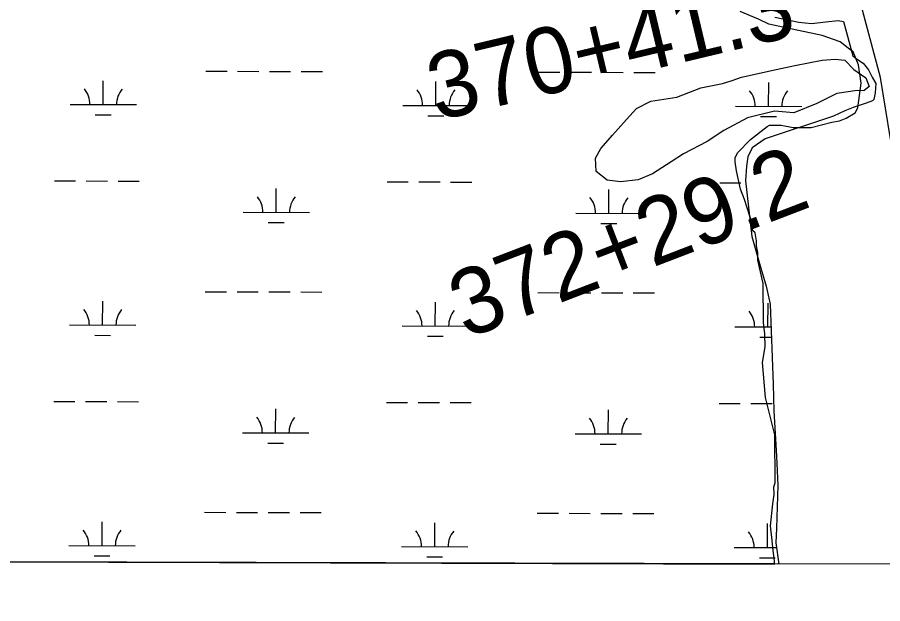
# Model space of a CAD drawing. Extents: x 3161665 to 3199565, y 885729 to 911164.
# Drawn here: x 3174412 to 3175718, y 891109 to 891993 of the extents above; entities that cross this region are included whole.
import ezdxf

# ---------------------------------------------------------------- set-up
doc = ezdxf.new("R2010")
doc.units = 0
for name, color, linetype in [('V-GRID-FRAM', 7, 'Continuous'), ('V-SITE-VEGE', 7, 'Continuous'), ('V-SURV-IDEN', 7, 'Continuous'), ('V-TOPO-SHOR', 7, 'Continuous'), ('V-WETL-SWMP', 7, 'Continuous')]:
    doc.layers.add(name, color=color, linetype=linetype)

msp = doc.modelspace()

# ---------------------------------------------------------------- linework, layer by layer
at = {"layer": 'V-GRID-FRAM'}
msp.add_lwpolyline([(3165935.6, 909383.8), (3197271.3, 909297.2), (3197229, 891108.8), (3165877.4, 891195.5), (3165935.6, 909383.8)], dxfattribs=at)
at = {"layer": 'V-SITE-VEGE'}
for p, q in [((3175530.5, 891990.7), (3175503, 892002.2)), ((3175546.2, 891983), (3175530.5, 891990.7)), ((3175581.4, 891975.5), (3175546.2, 891983)), ((3175626.5, 891966), (3175581.4, 891975.5)), ((3175653.9, 891956.5), (3175626.5, 891966)), ((3175665.7, 891946.8), (3175653.9, 891956.5)), ((3175673.6, 891941), (3175665.7, 891946.8)), ((3175681.6, 891921.5), (3175673.6, 891941)), ((3175685.7, 891894.2), (3175681.6, 891921.5)), ((3175680.2, 891857), (3175685.7, 891894.2)), ((3175662.7, 891841.2), (3175676.3, 891849.2)), ((3175676.3, 891849.2), (3175680.2, 891857)), ((3175610, 891827.1), (3175641.2, 891835.2)), ((3175641.2, 891835.2), (3175653, 891837.2)), ((3175653, 891837.2), (3175662.7, 891841.2)), ((3175518.3, 891808.8), (3175543.5, 891828.5)), ((3175543.5, 891828.5), (3175547.4, 891830.5)), ((3175547.4, 891830.5), (3175565, 891830.6)), ((3175565, 891830.6), (3175582.7, 891826.9)), ((3175582.7, 891826.9), (3175610, 891827.1)), ((3175498.9, 891789), (3175518.3, 891808.8)), ((3175495.1, 891781.2), (3175498.9, 891789)), ((3175495.1, 891775.3), (3175495.1, 891781.2)), ((3175497.2, 891761.7), (3175495.1, 891775.3)), ((3175503.3, 891734.3), (3175497.2, 891761.7)), ((3175509.3, 891718.7), (3175503.3, 891734.3)), ((3175517.3, 891693.4), (3175509.3, 891718.7)), ((3175521.3, 891681.7), (3175517.3, 891693.4)), ((3175521.4, 891671.9), (3175521.3, 891681.7)), ((3175525.3, 891668), (3175521.4, 891671.9)), ((3175527.4, 891656.3), (3175525.3, 891668)), ((3175527.4, 891648.5), (3175527.4, 891656.3)), ((3175529.5, 891638.8), (3175527.4, 891648.5)), ((3175529.6, 891627), (3175529.5, 891638.8)), ((3175537.7, 891591.9), (3175529.6, 891627)), ((3175538.2, 891533.2), (3175537.7, 891591.9)), ((3175540.3, 891515.7), (3175538.2, 891533.2)), ((3175540.4, 891496.1), (3175540.3, 891515.7)), ((3175536.7, 891472.6), (3175540.4, 891496.1)), ((3175541, 891419.9), (3175536.7, 891472.6)), ((3175555.2, 891363.3), (3175541, 891419.9)), ((3175555.8, 891291), (3175555.2, 891363.3)), ((3175553.9, 891285.1), (3175555.8, 891291)), ((3175552.1, 891259.7), (3175554, 891273.4)), ((3175554, 891273.4), (3175553.9, 891285.1)), ((3175548.5, 891226.4), (3175552.1, 891259.7)), ((3175550.6, 891208.8), (3175548.5, 891226.4)), ((3175552.7, 891189.3), (3175550.6, 891208.8)), ((3175554.8, 891173.7), (3175552.7, 891189.3)), ((3173270.6, 891175), (3175554.8, 891168.7)), ((3175554.8, 891168.7), (3175554.8, 891173.7))]:
    msp.add_line(p, q, dxfattribs=at)
at = {"layer": 'V-TOPO-SHOR'}
for points in [[(3175838, 891169.7), (3175813.2, 891379.1), (3175771.5, 891612.2), (3175729.7, 891809.8), (3175714.7, 891902.7), (3175685.4, 892011.6), (3175682.1, 892023.4)], [(3175307.5, 891811.8), (3175310.3, 891815.4), (3175331.6, 891839.3), (3175346.6, 891855.9), (3175368, 891866.9), (3175407.5, 891873), (3175443.3, 891886.9), (3175476.3, 891893.6), (3175490.6, 891898.1), (3175504.9, 891903.2), (3175557.3, 891914.4), (3175585.2, 891920.4), (3175626.8, 891928.6), (3175646.2, 891930.2), (3175660.6, 891928.9), (3175674.4, 891914.7), (3175692.4, 891901.9), (3175697.6, 891889), (3175689.7, 891882.5), (3175679.6, 891883.1), (3175648.8, 891878.5), (3175618.8, 891863.2), (3175583.7, 891849.3), (3175554.9, 891851.9), (3175514.1, 891841.5), (3175478.3, 891822.5), (3175453.3, 891805.8), (3175417.5, 891787.6), (3175399, 891775.2), (3175370.4, 891757), (3175348.9, 891748.2), (3175322.4, 891745.1), (3175302.2, 891747.8), (3175285.6, 891760.6), (3175284.7, 891780.7), (3175292.5, 891795.2), (3175307.4, 891811.8), (3175307.5, 891811.8)]]:
    msp.add_lwpolyline(points, dxfattribs=at)
at = {"layer": 'V-WETL-SWMP'}
for p, q in [((3175555.3, 891993.3), (3175591.3, 891986.1)), ((3175591.3, 891986.1), (3175610.5, 891983.9)), ((3175610.5, 891983.9), (3175632, 891986.6)), ((3175632, 891986.6), (3175650.7, 891988.4)), ((3175650.7, 891988.4), (3175658.8, 891986.8)), ((3175658.8, 891986.8), (3175672.7, 891935.4)), ((3175672.7, 891935.4), (3175679.8, 891929.9)), ((3175679.8, 891929.9), (3175688.5, 891924.3)), ((3175688.5, 891924.3), (3175696.3, 891914.3)), ((3175696.3, 891914.3), (3175702.3, 891902.9)), ((3174696.7, 891912), (3174728.7, 891911.9)), ((3174744.7, 891911.9), (3174776.7, 891911.8)), ((3174792.7, 891911.8), (3174824.7, 891911.7)), ((3174840.7, 891911.6), (3174872.7, 891911.6)), ((3175198.6, 891910.6), (3175230.6, 891910.6)), ((3175246.6, 891910.5), (3175278.6, 891910.4)), ((3175294.6, 891910.4), (3175326.6, 891910.3)), ((3175342.6, 891910.3), (3175374.6, 891910.2)), ((3175702.3, 891902.9), (3175707.6, 891893.3)), ((3174541.9, 891861.7), (3174542, 891897.7)), ((3175043.8, 891860.3), (3175043.9, 891896.3)), ((3175545.8, 891858.9), (3175545.9, 891894.9)), ((3175707.6, 891893.3), (3175706.7, 891879.6)), ((3175706.7, 891879.6), (3175704.8, 891869.3)), ((3174491.9, 891861.9), (3174591.9, 891861.6)), ((3174993.8, 891860.5), (3175093.8, 891860.2)), ((3175693.2, 891863.7), (3175673.3, 891857.2)), ((3175702.4, 891867.1), (3175693.2, 891863.7)), ((3175704.8, 891869.3), (3175702.4, 891867.1)), ((3175495.8, 891859.1), (3175595.8, 891858.8)), ((3175660.7, 891852.4), (3175643.8, 891844.2)), ((3175673.3, 891857.2), (3175660.7, 891852.4)), ((3174529.9, 891846.3), (3174553.9, 891846.3)), ((3175031.8, 891844.9), (3175055.8, 891844.9)), ((3175533.7, 891843.6), (3175557.7, 891843.5)), ((3175643.8, 891844.2), (3175540.6, 891809.9)), ((3175540.6, 891809.9), (3175521.2, 891796.3)), ((3175521.2, 891796.3), (3175514.6, 891782.7)), ((3175514.6, 891782.7), (3175512.5, 891768.6)), ((3175512.5, 891768.6), (3175510.7, 891746.7)), ((3174468.2, 891746.5), (3174500.2, 891746.4)), ((3174516.2, 891746.4), (3174548.2, 891746.3)), ((3174564.2, 891746.2), (3174596.2, 891746.1)), ((3174970.1, 891745.1), (3175002.1, 891745)), ((3175018.1, 891745), (3175050.1, 891744.9)), ((3175066.1, 891744.8), (3175098.1, 891744.8)), ((3175472, 891743.7), (3175504, 891743.6)), ((3175510.7, 891746.7), (3175520.3, 891662.7)), ((3174802.9, 891699.1), (3174803, 891735.1)), ((3175304.8, 891697.8), (3175304.9, 891733.8)), ((3174752.9, 891699.3), (3174852.9, 891699)), ((3175254.8, 891697.9), (3175354.8, 891697.6)), ((3174790.9, 891683.7), (3174814.9, 891683.7)), ((3175292.8, 891682.4), (3175316.8, 891682.3)), ((3175520.3, 891662.7), (3175534.3, 891615)), ((3175534.3, 891615), (3175541.9, 891587.6)), ((3175541.9, 891587.6), (3175548, 891560.6)), ((3174695.8, 891579.4), (3174727.8, 891579.3)), ((3174743.8, 891579.2), (3174775.8, 891579.1)), ((3174791.8, 891579.1), (3174823.8, 891579)), ((3174839.8, 891579), (3174871.8, 891578.9)), ((3175197.7, 891578), (3175229.7, 891577.9)), ((3175245.7, 891577.8), (3175277.7, 891577.8)), ((3175293.7, 891577.7), (3175325.7, 891577.6)), ((3175341.7, 891577.6), (3175373.7, 891577.5)), ((3174541, 891529), (3174541.1, 891565)), ((3175042.9, 891527.7), (3175043, 891563.7)), ((3175544.8, 891526.3), (3175544.9, 891562.3)), ((3175548, 891560.6), (3175552.6, 891439.8)), ((3174491, 891529.2), (3174591, 891528.9)), ((3174992.9, 891527.8), (3175092.9, 891527.5)), ((3175494.8, 891526.4), (3175549.3, 891526.3)), ((3174529, 891513.7), (3174553, 891513.6)), ((3175030.9, 891512.3), (3175054.9, 891512.2)), ((3175532.8, 891510.9), (3175549.9, 891510.8)), ((3175552.6, 891439.8), (3175553.9, 891399.7)), ((3174467.3, 891413.8), (3174499.3, 891413.7)), ((3174515.3, 891413.7), (3174547.3, 891413.6)), ((3174563.3, 891413.6), (3174595.3, 891413.5)), ((3174969.2, 891412.4), (3175001.2, 891412.3)), ((3175017.2, 891412.3), (3175049.2, 891412.2)), ((3175065.2, 891412.2), (3175097.2, 891412.1)), ((3175471.1, 891411), (3175503.1, 891411)), ((3175519.1, 891410.9), (3175551.1, 891410.8)), ((3174802, 891366.5), (3174802.1, 891402.5)), ((3175303.9, 891365.1), (3175304, 891401.1)), ((3175553.9, 891399.7), (3175557.8, 891331.1)), ((3174752, 891366.6), (3174852, 891366.3)), ((3175253.9, 891365.2), (3175353.9, 891364.9)), ((3174790, 891351.1), (3174814, 891351)), ((3175291.9, 891349.7), (3175315.9, 891349.6)), ((3175557.8, 891331.1), (3175559.5, 891287.2)), ((3175559.5, 891287.2), (3175557.7, 891223)), ((3174694.8, 891246.7), (3174726.8, 891246.6)), ((3174742.8, 891246.6), (3174774.8, 891246.5)), ((3174790.8, 891246.4), (3174822.8, 891246.3)), ((3174838.8, 891246.3), (3174870.8, 891246.2)), ((3175196.7, 891245.3), (3175228.7, 891245.2)), ((3175244.7, 891245.2), (3175276.7, 891245.1)), ((3175292.7, 891245), (3175324.7, 891244.9)), ((3175340.7, 891244.9), (3175372.7, 891244.8)), ((3174540.1, 891196.4), (3174540.2, 891232.4)), ((3175042, 891195), (3175042.1, 891231)), ((3175543.9, 891193.6), (3175544, 891229.6)), ((3175557.7, 891223), (3175556.7, 891200.5)), ((3174490.1, 891196.5), (3174590.1, 891196.2)), ((3174992, 891195.1), (3175092, 891194.8)), ((3175556.7, 891200.5), (3175561, 891168.7)), ((3175493.9, 891193.7), (3175557.6, 891193.6)), ((3175561, 891168.7), (3173270.6, 891175)), ((3174528.1, 891181), (3174552.1, 891180.9)), ((3175030, 891179.6), (3175054, 891179.5)), ((3175531.9, 891178.2), (3175555.9, 891178.1))]:
    msp.add_line(p, q, dxfattribs=at)
for centre, start, end in [((3174486.7, 891862.3), 359.0698, 40.6135), ((3174597.2, 891862), 139.0698, 180.6135), ((3174988.6, 891861), 359.0698, 40.6135), ((3175099.1, 891860.7), 139.0698, 180.6135), ((3175490.5, 891859.6), 359.0698, 40.6135), ((3175601, 891859.3), 139.0698, 180.6135), ((3174747.7, 891699.8), 359.0698, 40.6135), ((3174858.2, 891699.5), 139.0698, 180.6135), ((3175249.6, 891698.4), 359.0698, 40.6135), ((3175360.1, 891698.1), 139.0698, 180.6135), ((3174485.8, 891529.7), 359.0698, 40.6135), ((3174596.3, 891529.4), 139.0698, 180.6135), ((3174987.7, 891528.3), 359.0698, 40.6135), ((3175098.2, 891528), 139.0698, 180.6135), ((3175489.6, 891526.9), 359.0698, 40.6135), ((3174746.8, 891367.1), 359.0698, 40.6135), ((3174857.3, 891366.8), 139.0698, 180.6135), ((3175248.7, 891365.7), 359.0698, 40.6135), ((3175359.2, 891365.4), 139.0698, 180.6135), ((3174484.9, 891197), 359.0698, 40.6135), ((3174595.3, 891196.7), 139.0698, 180.6135), ((3174986.8, 891195.6), 359.0698, 40.6135), ((3175097.3, 891195.3), 139.0698, 180.6135), ((3175488.7, 891194.2), 359.0698, 40.6135)]:
    msp.add_arc(centre, 35.2, start, end, dxfattribs=at)

# ---------------------------------------------------------------- texts
at = {"layer": 'V-SURV-IDEN'}
for s, rotation, p in [('370+41.3', 13.3961, (3175045.1, 891836.8)), ('372+29.2', 20.9966, (3175089.1, 891507.7))]:
    msp.add_text(s, height=100, rotation=rotation, dxfattribs=at).set_placement(p)

doc.saveas('drawing.dxf')
